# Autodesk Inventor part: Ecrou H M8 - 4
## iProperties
Created: 2002-05
Part Number: Ecrou H M8 - 4
Material: Par défaut
Catalog Web Link: www.traceparts.com
Description: Ecrou Hexagonal - BEN 24032 - M8 - 4, Grade A, type 2
Document SubType Name: Modélisation
Designer: REVEST Pierre
Control State: 0
Master: False
Checked Out: False
Shininess: 20.0
Length Units: 11269
Angle Units: 11279
Time Units: 11290
Mass Units: 11283
Length Display Precision: 3
Angle Display Precision: 2
Density: 0.0
Volumn: 0.0
Area: 0.0
PropertySet Name: Model Information
Author: REVEST Pierre
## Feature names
1. Base1
